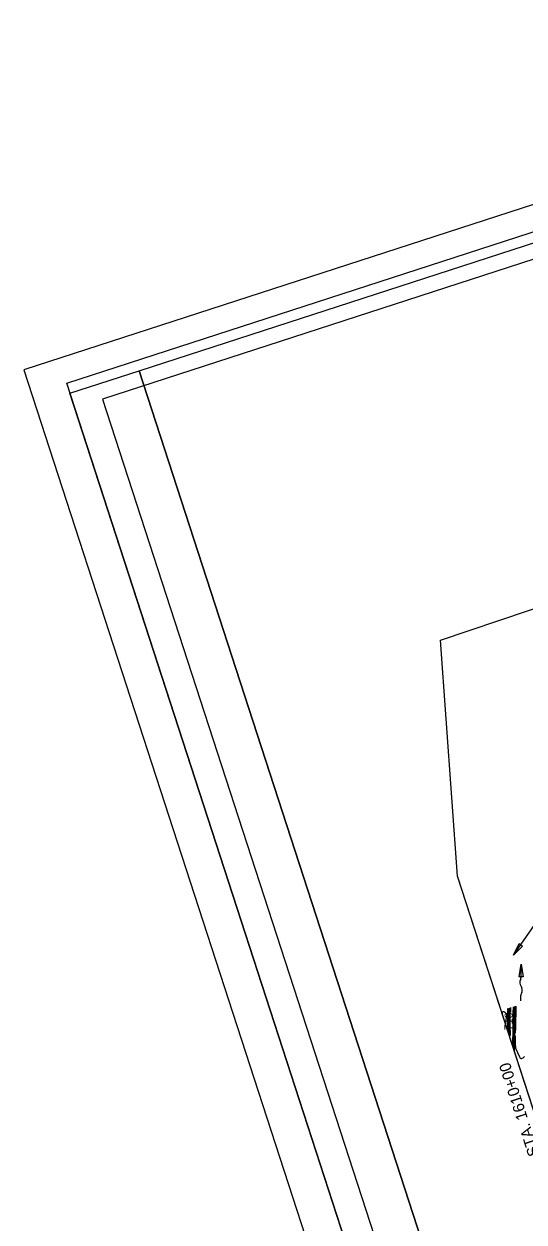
# Model space of a CAD drawing. Extents: x -468556195 to 3353078, y -306091294 to 1252632.
# Drawn here: x 1825053 to 1827114, y 532464 to 537403 of the extents above; entities that cross this region are included whole.
import ezdxf

# ---------------------------------------------------------------- set-up
doc = ezdxf.new("R2010")
doc.units = 0
for name, color, linetype in [('DT_X_Contour_Minor', 7, 'Continuous'), ('DT_X_Terrain_Ground_Line', 7, 'Continuous'), ('Level 19', 7, 'Continuous'), ('Level 31', 7, 'Continuous'), ('Level 40', 7, 'Continuous'), ('Level 63', 7, 'Continuous'), ('SC_Scratch1', 7, 'Continuous'), ('SH_Border', 7, 'Continuous'), ('SH_Cut_Line', 7, 'Continuous')]:
    doc.layers.add(name, color=color, linetype=linetype)

msp = doc.modelspace()

# ---------------------------------------------------------------- linework, layer by layer
at = {"layer": 'DT_X_Contour_Minor'}
for points in [[(1827023.7, 533322.2), (1827024.3, 533324.9), (1827025.5, 533328.7), (1827027.5, 533331.7), (1827030.4, 533332.2), (1827034.3, 533329.3), (1827038.2, 533324.2), (1827041, 533318.9), (1827041.9, 533314.6), (1827041.2, 533310.4), (1827039.8, 533305), (1827038.4, 533297.5), (1827037.4, 533288.9), (1827037.3, 533280.8), (1827037.5, 533279.8)], [(1827046.7, 533251.5), (1827047.1, 533272.2), (1827047.1, 533299.6), (1827047.3, 533334.1), (1827046.8, 533342), (1827046.5, 533343.4)], [(1827051, 533238.3), (1827051.3, 533251.9), (1827051.6, 533277.5), (1827051.5, 533302.9), (1827052, 533327.2), (1827052.3, 533341.6), (1827052.1, 533345.2)], [(1827055.4, 533224.5), (1827056, 533254.4), (1827056, 533282.7), (1827056, 533306.1), (1827056.7, 533333.4), (1827057, 533346.8)], [(1827058.9, 533329.3), (1827059.1, 533336.5), (1827059.3, 533347.6)], [(1827068.4, 533350.5), (1827067.6, 533325.6), (1827067, 533303.8), (1827067.1, 533274.1), (1827067, 533244.9), (1827066.4, 533210.1), (1827066, 533192)], [(1827070.4, 533351.2), (1827069.6, 533326.4), (1827069, 533303.5), (1827069, 533275.2), (1827068.8, 533244.7), (1827068.2, 533212.8), (1827067.7, 533186.8)], [(1827074.1, 533352.4), (1827074, 533343.2), (1827073.1, 533311.4), (1827072.7, 533285.8), (1827072.5, 533252.6), (1827072, 533227.2), (1827071.6, 533199.5), (1827071.1, 533176.1)], [(1827075, 533164.3), (1827074.9, 533182.5), (1827075.4, 533212.7), (1827075.9, 533244.1), (1827076.3, 533272.6), (1827076.8, 533302.3), (1827077.6, 533334.8), (1827078, 533353.6)], [(1827079.9, 533354.3), (1827079.9, 533353.6), (1827079.3, 533324.4), (1827078.5, 533291.6), (1827078, 533264.7), (1827077.6, 533243.8)], [(1827057.9, 533233.1), (1827058.3, 533253.4)], [(1827077.4, 533231.8), (1827077.2, 533204.3), (1827077.4, 533193.6), (1827077.9, 533187.3), (1827079.1, 533180.9), (1827079.3, 533179.4), (1827080.1, 533177.4), (1827086.7, 533162.8), (1827094.5, 533144.7), (1827096.6, 533141.4), (1827098.4, 533139.4), (1827100.7, 533138.1), (1827103.4, 533138), (1827106.5, 533139.1), (1827109.5, 533141.2), (1827115.2, 533146.4)]]:
    msp.add_lwpolyline(points, dxfattribs=at)
at = {"layer": 'DT_X_Terrain_Ground_Line'}
msp.add_line((1827446.8, 532019.1), (1826839.3, 533890.1), dxfattribs=at)
at = {"layer": 'Level 31'}
for p, q in [((1827093, 533474.8), (1827101.9, 533526.3)), ((1827101.6, 533473.3), (1827101.9, 533526.3)), ((1827101.9, 533526.3), (1827110.2, 533474.7)), ((1827110.2, 533474.7), (1827093, 533474.8)), ((1827098.1, 533443.6), (1827101.6, 533435)), ((1827099.9, 533464.8), (1827098.2, 533460.7)), ((1827101.6, 533435), (1827104.8, 533427.3)), ((1827100.5, 533376.3), (1827100.6, 533397.2)), ((1827104.4, 533409.4), (1827102.4, 533405.2))]:
    msp.add_line(p, q, dxfattribs=at)
for centre, radius, start, end in [((1827118.9, 533452.1), 22.4, 157.2839, 202.1277), ((1827079.2, 533473.5), 22.4, 337.3227, 359.6827), ((1827084, 533418.8), 22.4, 335.15, 22.2585), ((1827119.8, 533397.1), 19.2, 155.1999, 179.6827)]:
    msp.add_arc(centre, radius, start, end, dxfattribs=at)
at = {"layer": 'Level 40'}
for p, q in [((1827070.7, 533564.1), (1827093.1, 533611.4)), ((1827107.2, 533601.6), (1827070.7, 533564.1)), ((1827093.1, 533611.4), (1827107.2, 533601.6))]:
    msp.add_line(p, q, dxfattribs=at)
msp.add_lwpolyline([(1827070.7, 533564.1), (1827221.2, 533781.2), (1827292.5, 533804.4)], dxfattribs=at)
at = {"layer": 'Level 63'}
for points in [[(1825229.4, 535921.9), (1834930.2, 539071.3), (1836968, 532794.6), (1827267.2, 529645.1)], [(1827336.2, 529818.9), (1836809.4, 532894.5), (1834849.2, 538932.3), (1825375.9, 535856.7)]]:
    msp.add_lwpolyline(points, close=True, dxfattribs=at)
at = {"layer": 'SC_Scratch1'}
msp.add_lwpolyline([(1826839.3, 533890.1), (1826769.8, 534863.1), (1833950.4, 537284.3), (1834448.3, 536360.7), (1835055.9, 534489.2), (1835128.1, 533209.3), (1827818.5, 531160.4), (1827446.8, 532019.1)], close=True, dxfattribs=at)
at = {"layer": 'SH_Border'}
for points in [[(1825526.9, 535973.1), (1834657.8, 538937.5), (1836603.1, 532945.4), (1827472.3, 529981)], [(1825241.6, 535880.5), (1825526.9, 535973.1), (1827472.3, 529981), (1827186.9, 529888.4)]]:
    msp.add_lwpolyline(points, close=True, dxfattribs=at)
at = {"layer": 'SH_Cut_Line'}
msp.add_lwpolyline([(1827090.6, 529699.4), (1836792.1, 532849), (1834754.1, 539126.5), (1825052.6, 535976.8)], close=True, dxfattribs=at)

# ---------------------------------------------------------------- texts
at = {"layer": 'DT_X_Terrain_Ground_Line'}
msp.add_text('MATCH LINE                  STA. 1610+00', height=46.8, rotation=107.9864, dxfattribs=at).set_placement((1827391.9, 532085))
at = {"layer": 'Level 19'}
for s, height, rotation, p in [('710', 33, 89.0434, (1827065.7, 533254.3)), ('716', 4, 88.9803, (1827079.4, 533232.4))]:
    msp.add_text(s, height=height, rotation=rotation, dxfattribs=at).set_placement(p)

doc.saveas('drawing.dxf')
